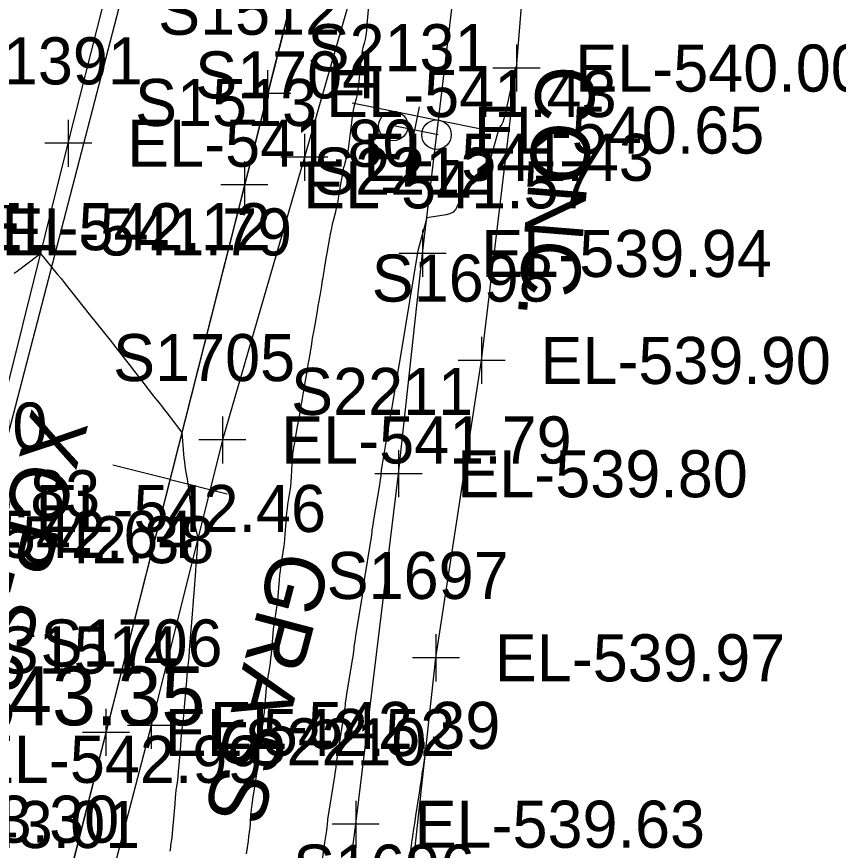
# Model space of a CAD drawing. Extents: x 1724534 to 1727318, y 657156 to 660047.
# Drawn here: x 1725525.9 to 1725595.7, y 659248.3 to 659319.2 of the extents above; entities that cross this region are included whole.
import ezdxf

# ---------------------------------------------------------------- set-up
doc = ezdxf.new("R2010")
doc.units = 0
for name, color, linetype in [('SURVEY - CENTERLINE - Preliminary', 7, 'Continuous'), ('SURVEY - CENTERLINE - Preliminary Text', 7, 'Continuous'), ('SURVEY - CONTOURS - Index with Text', 7, 'Continuous'), ('SURVEY - CONTOURS - Intermediate with optional Text', 7, 'Continuous'), ('SURVEY - CONTROL - Points - Elevations', 7, 'Continuous'), ('SURVEY - CONTROL with Text', 7, 'Continuous'), ('SURVEY - DRAINAGE - Area Shapes', 7, 'Continuous'), ('SURVEY - DTM - Breaklines', 7, 'Continuous'), ('SURVEY - DTM - Breaklines - Points - Elevations', 7, 'Continuous'), ('SURVEY - DTM - Breaklines - Points - Locators', 7, 'Continuous'), ('SURVEY - DTM - Breaklines - Points - Numbers', 7, 'Continuous'), ('SURVEY - TRAFFIC CONTROL - Signs - Points - Elevations', 7, 'Continuous'), ('SURVEY - TRAFFIC CONTROL - Signs - Points - Locators', 7, 'Continuous'), ('SURVEY - TRAFFIC CONTROL - Signs - Points - Numbers', 7, 'Continuous'), ('SURVEY - TRAFFIC CONTROL - Signs and Devices with Text', 7, 'Continuous'), ('SURVEY - TRANSPORTATION - Features', 7, 'Continuous'), ('SURVEY - TRANSPORTATION - Features - Points - Elevations', 7, 'Continuous'), ('SURVEY - TRANSPORTATION - Features - Points - Locators', 7, 'Continuous'), ('SURVEY - TRANSPORTATION - Features - Points - Numbers', 7, 'Continuous'), ('SURVEY - TRANSPORTATION - Features Text', 7, 'Continuous'), ('SURVEY - TRANSPORTATION - Roads', 7, 'Continuous'), ('SURVEY - TRANSPORTATION - Roads - Points - Elevations', 7, 'Continuous'), ('SURVEY - TRANSPORTATION - Roads - Points - Locators', 7, 'Continuous'), ('SURVEY - TRANSPORTATION - Roads - Points - Numbers', 7, 'Continuous'), ('SURVEY - UTILITIES - Electric (Lighting) - Points - Elevations', 7, 'Continuous'), ('SURVEY - VEGETATION - Features with Text', 7, 'Continuous')]:
    doc.layers.add(name, color=color, linetype=linetype)

msp = doc.modelspace()

# ---------------------------------------------------------------- linework, layer by layer
at = {"layer": 'SURVEY - CENTERLINE - Preliminary'}
msp.add_line((1725628.749, 659634.745), (1725510.016, 659165.778), dxfattribs=at)
msp.add_line((1725628.749, 659634.745), (1725510.016, 659165.778), dxfattribs=at)
msp.add_line((1725628.749, 659634.745), (1725510.016, 659165.778), dxfattribs=at)
at = {"layer": 'SURVEY - CENTERLINE - Preliminary Text'}
for q in [(1725534.044, 659281.055), (1725543.738, 659278.6)]:
    msp.add_line((1725538.891, 659279.828), q, dxfattribs=at)
at = {"layer": 'SURVEY - CONTOURS - Index with Text'}
for points in [[(1725568.359, 659315.085), (1725568.268, 659314.856), (1725568.252, 659314.823), (1725568.224, 659314.773), (1725567.522, 659311.557), (1725567.383, 659310.948), (1725567.267, 659310.491), (1725567.173, 659310.187), (1725567.101, 659310.035), (1725566.938, 659309.832), (1725566.866, 659309.694), (1725566.771, 659309.43), (1725566.652, 659309.041), (1725566.51, 659308.527), (1725566.101, 659306.989), (1725565.931, 659306.457), (1725565.725, 659306.016), (1725565.485, 659305.664), (1725565.211, 659305.403), (1725564.433, 659304.827), (1725564.163, 659304.601), (1725563.936, 659304.356), (1725563.753, 659304.092), (1725563.613, 659303.809), (1725563.3, 659303.028), (1725563.152, 659302.764), (1725562.946, 659302.56), (1725562.682, 659302.416), (1725562.358, 659302.33), (1725560.71, 659302.071), (1725559.992, 659299.365), (1725559.927, 659299.108), (1725558.522, 659290.679), (1725558.354, 659289.683), (1725557.709, 659285.819), (1725557.607, 659285.218), (1725556.894, 659280.953), (1725556.832, 659280.59), (1725556.813, 659280.272), (1725556.795, 659280.127), (1725556.751, 659279.832), (1725556.68, 659279.387), (1725556.187, 659276.411), (1725556.115, 659275.964), (1725556.07, 659275.666), (1725556.052, 659275.517), (1725556.039, 659275.317), (1725556.021, 659275.168), (1725555.976, 659274.872), (1725555.906, 659274.428), (1725555.42, 659271.472), (1725555.35, 659271.027), (1725555.305, 659270.728), (1725555.286, 659270.575), (1725555.271, 659270.363), (1725555.252, 659270.211), (1725555.208, 659269.914), (1725555.138, 659269.471), (1725554.659, 659266.533), (1725554.589, 659266.089), (1725554.545, 659265.789), (1725554.525, 659265.634), (1725554.508, 659265.412), (1725554.489, 659265.257), (1725554.445, 659264.958), (1725554.376, 659264.516), (1725553.902, 659261.594), (1725553.833, 659261.151), (1725553.788, 659260.85), (1725553.769, 659260.692), (1725553.75, 659260.461), (1725553.731, 659260.303), (1725553.687, 659260.004), (1725553.618, 659259.563), (1725553.03, 659255.918), (1725552.996, 659255.512), (1725552.977, 659255.352), (1725552.933, 659255.052), (1725552.865, 659254.612), (1725552.274, 659250.932), (1725552.233, 659250.475), (1725552.215, 659250.314), (1725552.175, 659250.012), (1725552.032, 659248.989), (1725551.704, 659246.672)], [(1725559.314, 659248.111), (1725559.408, 659248.729), (1725559.477, 659249.183), (1725559.52, 659249.471), (1725559.537, 659249.594), (1725559.549, 659249.701), (1725559.553, 659249.737), (1725559.556, 659249.762), (1725559.557, 659249.778), (1725559.558, 659249.783), (1725559.558, 659249.786), (1725559.572, 659249.878), (1725559.615, 659250.152), (1725559.685, 659250.608), (1725559.783, 659251.247), (1725560.083, 659253.193), (1725560.182, 659253.833), (1725560.252, 659254.294), (1725560.295, 659254.574), (1725560.309, 659254.675), (1725560.31, 659254.704), (1725560.316, 659254.745), (1725560.331, 659254.845), (1725560.356, 659255.005), (1725560.39, 659255.224), (1725560.576, 659256.387)]]:
    msp.add_lwpolyline(points, dxfattribs=at)
at = {"layer": 'SURVEY - CONTOURS - Intermediate with optional Text'}
for points in [[(1725555.745, 659320.036), (1725555.627, 659318.508), (1725555.582, 659317.984), (1725555.534, 659317.558), (1725555.484, 659317.23), (1725555.431, 659317.001), (1725555.287, 659316.521), (1725555.233, 659316.297), (1725555.179, 659315.984), (1725555.126, 659315.583), (1725555.073, 659315.093), (1725554.932, 659313.668), (1725554.879, 659313.174), (1725554.823, 659312.761), (1725554.765, 659312.427), (1725554.706, 659312.174), (1725554.545, 659311.607), (1725554.485, 659311.357), (1725554.425, 659311.034), (1725554.367, 659310.638), (1725554.308, 659310.167), (1725554.154, 659308.816), (1725554.096, 659308.342), (1725554.035, 659307.937), (1725553.974, 659307.599), (1725553.91, 659307.329), (1725553.739, 659306.699), (1725553.682, 659306.492), (1725553.642, 659306.344), (1725553.618, 659306.254), (1725553.609, 659306.218), (1725553.598, 659306.155), (1725553.567, 659305.971), (1725553.515, 659305.665), (1725553.442, 659305.237), (1725553.219, 659303.933), (1725553.138, 659303.474), (1725553.062, 659303.077), (1725552.989, 659302.74), (1725552.922, 659302.464), (1725552.748, 659301.808), (1725552.68, 659301.533), (1725552.608, 659301.2), (1725552.531, 659300.807), (1725552.449, 659300.356), (1725552.224, 659299.073), (1725552.146, 659298.628), (1725552.081, 659298.252), (1725552.029, 659297.947), (1725551.989, 659297.712), (1725551.901, 659297.18), (1725551.866, 659296.974), (1725551.83, 659296.755), (1725551.751, 659296.279), (1725551.64, 659295.611), (1725551.593, 659295.331), (1725551.535, 659294.993), (1725551.466, 659294.595), (1725551.387, 659294.139), (1725551.161, 659292.843), (1725551.081, 659292.385), (1725551.011, 659291.982), (1725550.952, 659291.634), (1725550.903, 659291.342), (1725550.736, 659290.345), (1725550.678, 659290.003), (1725550.61, 659289.609), (1725550.533, 659289.163), (1725550.314, 659287.905), (1725550.167, 659287.059), (1725550.107, 659286.709), (1725550.057, 659286.407), (1725549.933, 659285.668), (1725549.883, 659285.368), (1725549.824, 659285.022), (1725549.757, 659284.631), (1725549.681, 659284.195), (1725549.468, 659282.971), (1725549.398, 659282.569), (1725549.348, 659282.282), (1725549.308, 659282.052), (1725549.308, 659282.052), (1725549.308, 659282.052), (1725549.308, 659282.051), (1725549.308, 659282.05), (1725549.307, 659282.046), (1725549.304, 659281.991), (1725549.294, 659281.83), (1725549.278, 659281.563), (1725549.255, 659281.189), (1725549.185, 659280.05), (1725549.156, 659279.636), (1725549.119, 659279.249), (1725549.076, 659278.889), (1725549.027, 659278.556), (1725548.885, 659277.703), (1725548.835, 659277.372), (1725548.792, 659277.02), (1725548.755, 659276.645), (1725548.724, 659276.247), (1725548.651, 659275.159), (1725548.62, 659274.759), (1725548.582, 659274.377), (1725548.537, 659274.013), (1725548.485, 659273.666), (1725548.336, 659272.765), (1725548.284, 659272.421), (1725548.239, 659272.063), (1725548.2, 659271.691), (1725548.168, 659271.306), (1725548.093, 659270.262), (1725548.061, 659269.875), (1725548.022, 659269.497), (1725547.975, 659269.129), (1725547.921, 659268.77), (1725547.766, 659267.827), (1725547.712, 659267.47), (1725547.665, 659267.107), (1725547.625, 659266.739), (1725547.593, 659266.365), (1725547.515, 659265.36), (1725547.483, 659264.984), (1725547.442, 659264.61), (1725547.394, 659264.239), (1725547.338, 659263.869), (1725547.178, 659262.888), (1725547.122, 659262.521), (1725547.074, 659262.154), (1725547.033, 659261.789), (1725547, 659261.424), (1725546.921, 659260.453), (1725546.888, 659260.087), (1725546.847, 659259.717), (1725546.797, 659259.342), (1725546.74, 659258.964), (1725546.575, 659257.949), (1725546.521, 659257.616), (1725546.483, 659257.378), (1725546.452, 659257.187), (1725546.452, 659257.186), (1725546.448, 659257.142), (1725546.437, 659257.01), (1725546.419, 659256.791), (1725546.317, 659255.547), (1725546.283, 659255.191), (1725546.242, 659254.824), (1725546.191, 659254.447), (1725546.132, 659254.059), (1725545.908, 659252.666), (1725545.868, 659252.418), (1725545.843, 659252.265), (1725545.835, 659252.209), (1725545.832, 659252.188), (1725545.815, 659252.006), (1725545.796, 659251.79), (1725545.771, 659251.491), (1725545.693, 659250.585), (1725545.66, 659250.236), (1725545.62, 659249.872), (1725545.573, 659249.491), (1725545.519, 659249.093), (1725545.365, 659248.012)], [(1725525.653, 659297.354), (1725525.897, 659297.522), (1725525.898, 659297.523), (1725526.048, 659297.636), (1725526.235, 659297.777), (1725526.497, 659297.975), (1725527.894, 659299.028), (1725529.335, 659297.255), (1725529.626, 659296.896), (1725529.881, 659296.578), (1725530.102, 659296.302), (1725530.287, 659296.067), (1725530.735, 659295.497), (1725530.942, 659295.235), (1725532.031, 659293.871), (1725533.313, 659292.274), (1725533.797, 659291.667), (1725534.29, 659291.045), (1725534.79, 659290.407), (1725535.298, 659289.754), (1725536.665, 659287.991), (1725537.128, 659287.394), (1725537.492, 659286.924), (1725537.759, 659286.583), (1725537.926, 659286.369), (1725538.243, 659285.97), (1725538.373, 659285.804), (1725538.527, 659285.607), (1725538.903, 659285.118), (1725539.889, 659283.83), (1725540.038, 659282.023), (1725540.072, 659281.654), (1725540.108, 659281.322), (1725540.147, 659281.027), (1725540.188, 659280.769), (1725540.303, 659280.13), (1725540.345, 659279.879), (1725540.387, 659279.606), (1725540.428, 659279.31), (1725540.468, 659278.993), (1725540.572, 659278.116), (1725540.618, 659277.779), (1725540.677, 659277.426), (1725540.748, 659277.057), (1725540.832, 659276.671), (1725541.252, 659274.836), (1725541.191, 659273.913), (1725541.17, 659273.611), (1725541.164, 659273.53), (1725541.161, 659273.496), (1725541.156, 659273.467), (1725541.148, 659273.369), (1725541.128, 659273.098), (1725541.095, 659272.654), (1725541.051, 659272.037), (1725540.915, 659270.16), (1725540.87, 659269.538), (1725540.835, 659269.08), (1725540.811, 659268.787), (1725540.798, 659268.658), (1725540.778, 659268.532), (1725540.765, 659268.407), (1725540.706, 659267.689), (1725540.66, 659267.096), (1725540.523, 659265.307), (1725540.476, 659264.711), (1725540.439, 659264.262), (1725540.412, 659263.961), (1725540.394, 659263.808), (1725540.36, 659263.597), (1725540.342, 659263.447), (1725540.315, 659263.158), (1725540.277, 659262.727), (1725540.045, 659259.871), (1725540.007, 659259.43), (1725539.976, 659259.122), (1725539.955, 659258.948), (1725539.908, 659258.661), (1725539.893, 659258.567), (1725539.882, 659258.499), (1725539.876, 659258.459), (1725539.873, 659258.445), (1725539.873, 659258.443), (1725539.867, 659258.366), (1725539.848, 659258.136), (1725539.816, 659257.753), (1725539.772, 659257.216), (1725539.637, 659255.582), (1725539.59, 659255.029), (1725539.55, 659254.595), (1725539.518, 659254.281), (1725539.493, 659254.087), (1725539.435, 659253.727), (1725539.416, 659253.608), (1725539.402, 659253.523), (1725539.393, 659253.47), (1725539.39, 659253.451), (1725539.389, 659253.444), (1725539.383, 659253.368), (1725539.363, 659253.145), (1725539.332, 659252.777), (1725539.287, 659252.262), (1725539.152, 659250.694), (1725539.105, 659250.159), (1725539.065, 659249.731), (1725539.032, 659249.411), (1725539.006, 659249.197), (1725538.945, 659248.77), (1725538.919, 659248.559), (1725538.886, 659248.248)]]:
    msp.add_lwpolyline(points, dxfattribs=at)
at = {"layer": 'SURVEY - DRAINAGE - Area Shapes'}
msp.add_lwpolyline([(1725457.865, 659006.777), (1725413.857, 659016.262), (1725297.605, 659050.843), (1725314.042, 659296.608), (1725386.76, 659493.901), (1725483.401, 659755.229), (1725623.949, 659732.704), (1725676.22, 659724.326), (1725634.82, 659466.017), (1725543.324, 659353.721), (1725499.683, 659185.923), (1725479.088, 659106.738)], close=True, dxfattribs=at)
at = {"layer": 'SURVEY - DTM - Breaklines'}
msp.add_lwpolyline([(1725525.942, 659009.271), (1725526.399, 659011.158), (1725528.918, 659041.105), (1725531.461, 659071.052), (1725534.8, 659101.37), (1725536.346, 659131.334), (1725539.898, 659161.171), (1725544.971, 659191.09), (1725550.75, 659220.691), (1725554.674, 659250.537), (1725558.308, 659280.317), (1725560.346, 659299.038), (1725563.922, 659328.825), (1725567.992, 659357.481)], dxfattribs=at)
at = {"layer": 'SURVEY - DTM - Breaklines - Points - Locators'}
for p, q in [((1725560.346, 659301.038), (1725560.346, 659297.038)), ((1725562.346, 659299.038), (1725558.346, 659299.038)), ((1725558.308, 659282.317), (1725558.308, 659278.317)), ((1725560.308, 659280.317), (1725556.308, 659280.317)), ((1725554.674, 659252.537), (1725554.674, 659248.537)), ((1725556.674, 659250.537), (1725552.674, 659250.537))]:
    msp.add_line(p, q, dxfattribs=at)
at = {"layer": 'SURVEY - TRAFFIC CONTROL - Signs - Points - Locators'}
for p, q in [((1725559.313, 659307.563), (1725560.103, 659311.485)), ((1725561.669, 659309.129), (1725557.747, 659309.919))]:
    msp.add_line(p, q, dxfattribs=at)
at = {"layer": 'SURVEY - TRAFFIC CONTROL - Signs and Devices with Text'}
msp.add_line((1725554.362, 659311.85), (1725565.341, 659309.638), dxfattribs=at)
for centre in [(1725557.861, 659309.87), (1725561.538, 659309.129)]:
    msp.add_circle(centre, 1.25, dxfattribs=at)
at = {"layer": 'SURVEY - TRANSPORTATION - Features'}
msp.add_lwpolyline([(1725558.747, 659239.804), (1725561.49, 659264.678), (1725565.369, 659289.947), (1725568.335, 659314.791), (1725569.778, 659332.675), (1725572.178, 659357.586), (1725563.842, 659357.376), (1725557.203, 659331.254), (1725550.316, 659307.208), (1725543.339, 659283.189), (1725537.281, 659258.937), (1725530.962, 659234.747)], dxfattribs=at)
at = {"layer": 'SURVEY - TRANSPORTATION - Features - Points - Locators'}
for p, q in [((1725568.335, 659316.791), (1725568.335, 659312.791)), ((1725570.335, 659314.791), (1725566.335, 659314.791)), ((1725550.316, 659309.208), (1725550.316, 659305.208)), ((1725552.316, 659307.208), (1725548.316, 659307.208)), ((1725565.369, 659291.947), (1725565.369, 659287.947)), ((1725567.369, 659289.947), (1725563.369, 659289.947)), ((1725543.339, 659285.189), (1725543.339, 659281.189)), ((1725545.339, 659283.189), (1725541.339, 659283.189)), ((1725561.49, 659266.678), (1725561.49, 659262.678)), ((1725563.49, 659264.678), (1725559.49, 659264.678)), ((1725537.281, 659260.937), (1725537.281, 659256.937)), ((1725539.281, 659258.937), (1725535.281, 659258.937))]:
    msp.add_line(p, q, dxfattribs=at)
at = {"layer": 'SURVEY - TRANSPORTATION - Roads'}
for points in [[(1725509.717, 659226.971), (1725517.054, 659256.051), (1725522.463, 659277.37), (1725530.246, 659308.405), (1725536.116, 659331.674), (1725536.614, 659333.611), (1725542.122, 659354.908), (1725554.364, 659403.386), (1725567.129, 659453.798), (1725567.617, 659455.737), (1725576.381, 659490.656), (1725576.873, 659492.594), (1725587.785, 659535.219), (1725588.276, 659537.157), (1725594.628, 659562.367), (1725602.882, 659595.344), (1725603.37, 659597.283), (1725609.346, 659620.521)], [(1725624.67, 659618.957), (1725609.021, 659556.912), (1725594.317, 659498.747), (1725580.515, 659444.472), (1725570.134, 659403.773), (1725561.33, 659368.865), (1725557.927, 659355.285), (1725547.165, 659312.624), (1725545.206, 659304.869), (1725533.446, 659258.339), (1725527.51, 659235.091)]]:
    msp.add_lwpolyline(points, dxfattribs=at)
at = {"layer": 'SURVEY - TRANSPORTATION - Roads - Points - Locators'}
for p, q in [((1725547.165, 659314.624), (1725547.165, 659310.624)), ((1725549.165, 659312.624), (1725545.165, 659312.624)), ((1725530.246, 659310.405), (1725530.246, 659306.405)), ((1725532.246, 659308.405), (1725528.246, 659308.405)), ((1725545.206, 659306.869), (1725545.206, 659302.869)), ((1725547.206, 659304.869), (1725543.206, 659304.869)), ((1725533.446, 659260.339), (1725533.446, 659256.339)), ((1725535.446, 659258.339), (1725531.446, 659258.339))]:
    msp.add_line(p, q, dxfattribs=at)

# ---------------------------------------------------------------- texts
at = {"layer": 'SURVEY - CONTROL - Points - Elevations'}
msp.add_text('EL-543.35', height=5, dxfattribs=at).set_placement((1725511.025, 659258.941))
at = {"layer": 'SURVEY - CONTROL with Text'}
msp.add_text('XCP-S28', height=5, rotation=255.21068, dxfattribs=at).set_placement((1725527.155, 659285.953))
at = {"layer": 'SURVEY - DTM - Breaklines - Points - Elevations'}
for s, p in [('EL-542.12', (1725522.787, 659299.313)), ('EL-539.94', (1725565.346, 659297.038)), ('EL-539.80', (1725563.308, 659278.317)), ('EL-542.64', (1725516.183, 659273.168)), ('EL-543.30', (1725509.884, 659248.966)), ('EL-539.63', (1725559.674, 659248.537))]:
    msp.add_text(s, height=4, dxfattribs=at).set_placement(p)
at = {"layer": 'SURVEY - DTM - Breaklines - Points - Numbers'}
for s, p in [('S2212', (1725551.058, 659304.038)), ('S2211', (1725549.178, 659285.317)), ('S2210', (1725545.213, 659255.537))]:
    msp.add_text(s, height=4, dxfattribs=at).set_placement(p)
at = {"layer": 'SURVEY - TRAFFIC CONTROL - Signs - Points - Elevations'}
msp.add_text('EL-540.65', height=4, dxfattribs=at).set_placement((1725564.708, 659307.524))
at = {"layer": 'SURVEY - TRAFFIC CONTROL - Signs - Points - Numbers'}
msp.add_text('S2131', height=4, dxfattribs=at).set_placement((1725550.578, 659314.524))
at = {"layer": 'SURVEY - TRANSPORTATION - Features - Points - Elevations'}
for s, p in [('EL-540.00', (1725573.335, 659312.791)), ('EL-541.43', (1725555.316, 659305.208)), ('EL-541.79', (1725524.577, 659298.865)), ('EL-539.90', (1725570.369, 659287.947)), ('EL-541.79', (1725548.339, 659281.189)), ('EL-542.38', (1725517.973, 659272.714)), ('EL-539.97', (1725566.49, 659262.678)), ('EL-542.39', (1725542.281, 659256.937)), ('EL-543.01', (1725511.673, 659248.514))]:
    msp.add_text(s, height=4, dxfattribs=at).set_placement(p)
at = {"layer": 'SURVEY - TRANSPORTATION - Features - Points - Numbers'}
for s, p in [('S1704', (1725541.028, 659312.208)), ('S1698', (1725556.034, 659294.947)), ('S1705', (1725534.051, 659288.189)), ('S1697', (1725552.202, 659269.678)), ('S1706', (1725527.883, 659263.937)), ('S1696', (1725549.349, 659244.804))]:
    msp.add_text(s, height=4, dxfattribs=at).set_placement(p)
at = {"layer": 'SURVEY - TRANSPORTATION - Features Text'}
msp.add_text('CONC.', height=5, rotation=265.38699, dxfattribs=at).set_placement((1725570.163, 659315.177))
at = {"layer": 'SURVEY - TRANSPORTATION - Roads - Points - Elevations'}
for s, p in [('EL-541.43', (1725552.165, 659310.624)), ('EL-541.80', (1725535.246, 659306.405)), ('EL-541.57', (1725550.206, 659302.869)), ('EL-542.46', (1725527.463, 659275.37)), ('EL-542.52', (1725538.446, 659256.339)), ('EL-542.99', (1725522.054, 659254.051))]:
    msp.add_text(s, height=4, dxfattribs=at).set_placement(p)
at = {"layer": 'SURVEY - TRANSPORTATION - Roads - Points - Numbers'}
for s, p in [('S1512', (1725537.877, 659317.624)), ('S1391', (1725521.116, 659313.405)), ('S1513', (1725535.918, 659309.869)), ('S1390', (1725513.002, 659282.37)), ('S1514', (1725524.158, 659263.339))]:
    msp.add_text(s, height=4, dxfattribs=at).set_placement(p)
at = {"layer": 'SURVEY - UTILITIES - Electric (Lighting) - Points - Elevations'}
msp.add_text('EL-543.83', height=4, dxfattribs=at).set_placement((1725508.268, 659276.624))
at = {"layer": 'SURVEY - VEGETATION - Features with Text'}
msp.add_text('GRASS', height=5, rotation=255.21068, dxfattribs=at).set_placement((1725547.732, 659274.049))

doc.saveas('drawing.dxf')
